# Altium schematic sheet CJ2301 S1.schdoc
size 127 x 101 mm
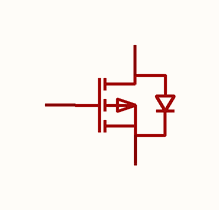
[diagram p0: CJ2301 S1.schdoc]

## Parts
Q?  cj2301 s1  [SOT-23-3_L3.0-W1.7-P0.95-LS2.9-BR]  (value not drawn)

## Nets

Not connected (* = marked no-connect by the designer): Q? 1(G) 2(S) 3(D)

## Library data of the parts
Q? = cj2301 s1: 数量:1个P沟道;漏源电压(Vdss):20V;连续漏极电流(Id):2.3A;导通电阻(RDS(on)):142mΩ@2.5V;耗散功率(Pd):350mW;阈值电压(Vgs(th)):1V;; Manufacturer: CJ(江苏长电/长晶); AddInBom: yes; ModelId: 89cb27a44ab2466697082bb9fd73a7d0; ModelName: SOT-23-3L_L2.9-W1.6-H1.1-LS2.8-P0.95; ModelTransform: 114.173,110.236,0,90,0,0,0,0,0; Number: 1个P沟道; Drain to Source Voltage: 20V; Current - Continuous Drain(Id): 2.3A; Pd - Power Dissipation: 350mW; Gate Threshold Voltage (Vgs(th)): 1V; Gate Charge(Qg): 5.5nC; Input Capacitance(Ciss): 405pF; Reverse Transfer Capacitance (Crss@Vds): 55pF; Type: P沟道; Output Capacitance(Coss): 75pF; Vgs: ±8V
